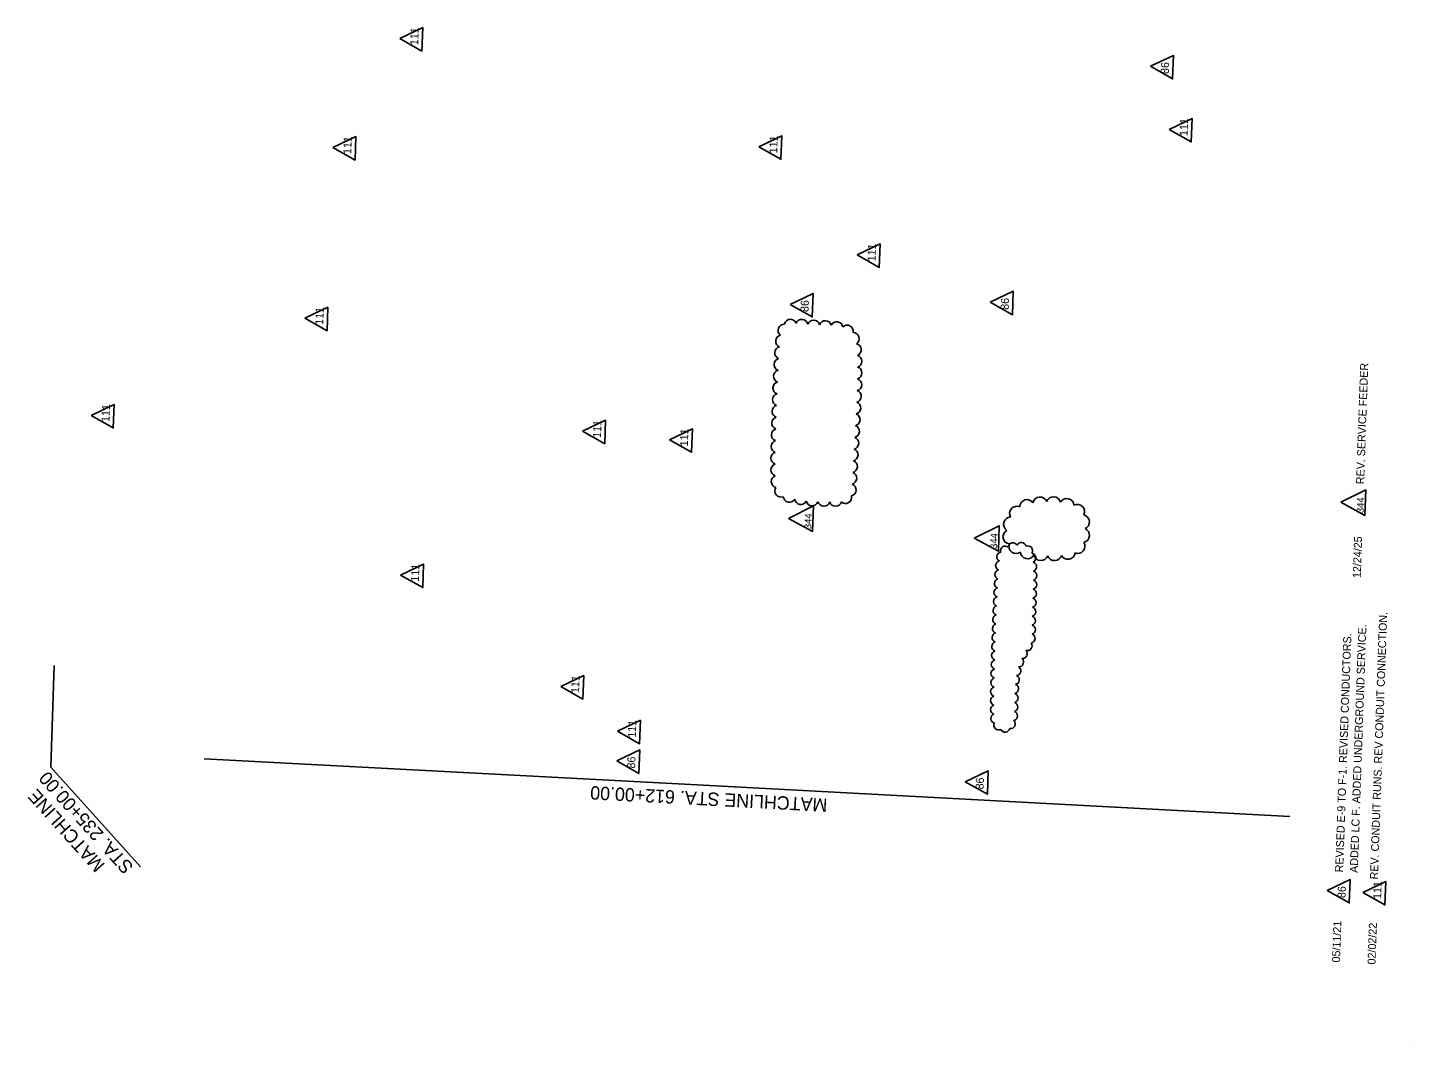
# Model space of a CAD drawing. Extents: x 928669 to 929521, y 636891 to 638153.
# Drawn here: x 928669 to 929497, y 636891 to 637500 of the extents above; entities that cross this region are included whole.
import ezdxf

# ---------------------------------------------------------------- set-up
doc = ezdxf.new("R2010")
doc.units = 0
for name, color, linetype in [('AdhocPoint_dp', 7, 'Continuous'), ('Cloud_dp', 7, 'Continuous'), ('PlotBorder_dp', 7, 'Continuous')]:
    doc.layers.add(name, color=color, linetype=linetype)

msp = doc.modelspace()

# ---------------------------------------------------------------- linework, layer by layer
at = {"layer": 'AdhocPoint_dp'}
msp.add_line((929497.23, 636890.88), (929497.23, 636890.88), dxfattribs=at)
at = {"layer": 'Cloud_dp'}
for points in [[(928892.18, 637493.38), (928905.49, 637485.87), (928905.98, 637499.95)], [(929342.46, 637476.74), (929355.77, 637469.23), (929356.26, 637483.31)], [(929353.7, 637438.9), (929367.01, 637431.39), (929367.5, 637445.47)], [(928852.01, 637428.07), (928865.32, 637420.55), (928865.81, 637434.63)], [(929107.53, 637428.51), (929120.84, 637421), (929121.33, 637435.07)], [(929166.5, 637363.72), (929179.81, 637356.21), (929180.3, 637370.28)], [(929126.34, 637333.99), (929139.65, 637326.48), (929140.14, 637340.55)], [(929246.44, 637335.3), (929259.74, 637327.79), (929260.24, 637341.87)], [(928835.21, 637325.69), (928848.52, 637318.18), (928849.01, 637332.25)], [(928706.97, 637267.46), (928720.28, 637259.95), (928720.77, 637274.02)], [(929001.81, 637257.92), (929015.12, 637250.41), (929015.62, 637264.49)], [(929053.95, 637252.83), (929067.26, 637245.32), (929067.75, 637259.4)], [(929456.7, 637215.31), (929471.17, 637207.46), (929471.71, 637222.78)], [(929125.38, 637205.69), (929139.85, 637197.84), (929140.4, 637213.16)], [(929236.82, 637193.83), (929251.29, 637185.99), (929251.84, 637201.3)], [(928892.62, 637171.72), (928905.92, 637164.21), (928906.42, 637178.28)], [(928988.69, 637104.86), (929001.99, 637097.34), (929002.49, 637111.42)], [(929022.71, 637078.07), (929036.02, 637070.56), (929036.51, 637084.63)], [(929022.35, 637060.26), (929035.66, 637052.75), (929036.15, 637066.82)], [(929231.39, 637047.73), (929244.7, 637040.22), (929245.19, 637054.29)], [(929448.5, 636982.61), (929461.8, 636975.1), (929462.3, 636989.17)], [(929469.81, 636981.4), (929483.12, 636973.89), (929483.61, 636987.96)]]:
    msp.add_lwpolyline(points, close=True, dxfattribs=at)
for centre, radius, start, end in [((929122.8, 637318.45), 3.69, 87.80017, 232.80017), ((929126.55, 637321.38), 3.69, 23.15755, 168.15755), ((929133.32, 637321.36), 3.69, 11.51014, 156.51014), ((929140.39, 637320.83), 3.69, 14.85135, 159.85135), ((929147.43, 637320.54), 3.69, 15.49782, 160.49782), ((929154.29, 637319.89), 3.69, 8.73713, 153.73713), ((929121.35, 637311.91), 3.69, 102.26773, 247.26773), ((929160.55, 637317.85), 3.69, 350.07913, 135.07913), ((929164.06, 637313.53), 3.69, 303.10209, 88.10209), ((929120.8, 637304.93), 3.69, 103.71595, 248.71595), ((929165.27, 637306.84), 3.69, 292.40552, 77.40552), ((929120.38, 637297.92), 3.69, 104.41777, 249.41777), ((929165.66, 637299.89), 3.69, 288.97914, 73.97914), ((929120.03, 637290.91), 3.69, 104.85392, 249.85392), ((929165.6, 637285.88), 3.69, 285.91131, 70.91131), ((929165.72, 637292.89), 3.69, 287.12059, 72.12059), ((929119.72, 637283.88), 3.69, 105.15885, 250.15885), ((929165.36, 637278.87), 3.69, 285.04439, 70.04439), ((929119.2, 637269.83), 3.69, 105.57058, 250.57058), ((929119.45, 637276.86), 3.69, 105.38753, 250.38753), ((929165.02, 637271.86), 3.69, 284.38636, 69.38636), ((929118.98, 637262.81), 3.69, 105.77043, 250.77043), ((929164.62, 637264.84), 3.69, 284.15826, 69.15826), ((929118.78, 637255.78), 3.69, 106.03107, 251.03107), ((929164.21, 637257.82), 3.69, 284.16856, 69.16856), ((929118.62, 637248.76), 3.69, 106.39157, 251.39157), ((929163.8, 637250.79), 3.69, 284.18212, 69.18212), ((929118.52, 637241.73), 3.69, 106.93873, 251.93873), ((929162.99, 637236.75), 3.69, 284.23075, 69.23075), ((929163.4, 637243.77), 3.69, 284.20115, 69.20115), ((929118.51, 637234.72), 3.69, 107.92679, 252.92679), ((929118.74, 637227.75), 3.69, 110.9032, 255.9032), ((929162.6, 637229.73), 3.69, 284.28717, 69.28717), ((929120.89, 637222.09), 3.69, 145.68846, 290.68846), ((929162.22, 637222.7), 3.69, 284.53316, 69.53316), ((929125.86, 637219.04), 3.69, 186.14464, 331.14464), ((929132.75, 637217.72), 3.69, 187.22191, 332.22191), ((929139.58, 637216.91), 3.69, 194.26719, 339.26719), ((929146.56, 637216.68), 3.69, 196.86603, 341.86603), ((929153.58, 637216.64), 3.69, 197.46796, 342.46796), ((929159.55, 637218.28), 3.69, 228.29205, 13.29205), ((929268.49, 637212.58), 4.34, 35.308, 180.308), ((929276.26, 637214.15), 4.34, 22.48218, 167.48218), ((929284.33, 637214.27), 4.34, 14.21001, 159.21001), ((929292.31, 637213.21), 4.34, 5.59978, 150.59978), ((929258.73, 637202.11), 4.34, 91.83987, 236.83987), ((929262.34, 637208.62), 4.34, 65.21552, 210.21552), ((929298.62, 637209.78), 4.34, 332.37306, 117.37306), ((929301.55, 637203.53), 4.34, 292.94928, 77.94928), ((929258.39, 637194.65), 4.34, 117.96985, 262.96985), ((929301.59, 637195.53), 4.34, 282.583, 67.583), ((929259.97, 637188.16), 2.83, 28.78334, 173.78334), ((929261.96, 637188.92), 4.34, 160.87737, 305.87737), ((929265.04, 637188.38), 2.83, 11.26339, 156.26339), ((929298.89, 637188.94), 4.33, 247.85066, 32.85066), ((929253.12, 637182.6), 2.83, 98.21199, 243.21199), ((929255.42, 637186.23), 2.83, 52.10778, 197.10778), ((929268.82, 637185.8), 4.34, 185.10829, 330.10829), ((929268.9, 637186.32), 2.83, 327.34776, 112.34776), ((929270.86, 637181.99), 2.83, 296.42176, 81.42176), ((929276.77, 637184.74), 4.34, 194.71107, 339.71107), ((929284.93, 637184.68), 4.34, 199.49595, 344.49595), ((929292.96, 637185.51), 4.34, 207.29676, 352.29676), ((929252.06, 637171.94), 2.83, 103.74095, 248.74095), ((929252.46, 637177.31), 2.83, 102.68653, 247.68653), ((929271.4, 637176.72), 2.83, 290.28256, 75.28256), ((929271.52, 637171.36), 2.83, 287.39433, 72.39433), ((929251.73, 637166.56), 2.83, 104.29457, 249.29457), ((929271.44, 637165.99), 2.83, 285.74847, 70.74847), ((929251.19, 637155.78), 2.83, 104.90417, 249.90417), ((929251.45, 637161.17), 2.83, 104.6505, 249.6505), ((929271.07, 637155.2), 2.83, 285.49782, 70.49782), ((929271.26, 637160.59), 2.83, 285.49782, 70.49782), ((929250.96, 637150.39), 2.83, 105.0968, 250.0968), ((929270.88, 637149.8), 2.83, 285.49782, 70.49782), ((929250.53, 637139.6), 2.83, 105.37448, 250.37448), ((929250.74, 637144.99), 2.83, 105.24953, 250.24953), ((929270.69, 637144.4), 2.83, 285.49782, 70.49782), ((929270.68, 637138.95), 2.83, 289.2147, 74.2147), ((929250.33, 637134.2), 2.83, 105.47977, 250.47977), ((929270.46, 637133.69), 2.83, 280.90735, 65.90735), ((929249.98, 637123.41), 2.83, 105.71597, 250.71597), ((929250.15, 637128.81), 2.83, 105.58748, 250.58748), ((929265.83, 637124.53), 2.83, 260.43465, 45.43465), ((929268.72, 637129.23), 2.83, 251.48331, 36.48331), ((929249.67, 637112.62), 2.83, 106.0666, 251.0666), ((929249.81, 637118.02), 2.83, 105.87187, 250.87187), ((929261.97, 637114.26), 2.83, 274.53949, 59.53949), ((929263.59, 637119.53), 2.83, 266.29935, 51.29935), ((929249.55, 637107.23), 2.83, 106.31958, 251.31958), ((929261.01, 637108.87), 2.83, 280.32638, 65.32638), ((929249.4, 637096.44), 2.83, 107.18967, 252.18967), ((929249.45, 637101.83), 2.83, 106.66732, 251.66732), ((929260.29, 637098.02), 2.83, 285.49782, 70.49782), ((929260.53, 637103.43), 2.83, 284.42974, 69.42974), ((929249.41, 637091.05), 2.83, 108.11302, 253.11302), ((929260.1, 637092.62), 2.83, 285.49782, 70.49782), ((929249.59, 637085.69), 2.83, 110.65574, 255.65574), ((929251.41, 637081.66), 2.83, 152.9623, 297.9623), ((929258.61, 637082.5), 2.83, 259.7863, 44.7863), ((929259.89, 637087.23), 2.83, 284.99439, 69.99439), ((929255.33, 637080.29), 2.83, 203.38501, 348.38501)]:
    msp.add_arc(centre, radius, start, end, dxfattribs=at)
at = {"layer": 'PlotBorder_dp'}
for p, q in [((928682.87, 637056.6), (928684.89, 637117.41)), ((928736.73, 636996.72), (928682.87, 637056.6))]:
    msp.add_line(p, q, dxfattribs=at)
msp.add_lwpolyline([(929426.17, 637026.85), (929066.68, 637046.02), (928774.81, 637061.58)], dxfattribs=at)

# ---------------------------------------------------------------- texts
at = {"layer": 'Cloud_dp'}
for s, height, p in [('111', 4.8, (928903.2, 637489.36)), ('86', 4.8, (929353.45, 637472.09)), ('111', 4.8, (929364.72, 637434.88)), ('111', 4.8, (928863.03, 637424.05)), ('111', 4.8, (929118.55, 637424.49)), ('111', 4.8, (929177.52, 637359.7)), ('111', 4.8, (928846.23, 637321.67)), ('86', 4.8, (929137.33, 637329.34)), ('86', 4.8, (929257.43, 637330.65)), ('REV. SERVICE FEEDER', 4.8, (929470.64, 637226.11)), ('111', 4.8, (928717.99, 637263.44)), ('111', 4.8, (929012.83, 637253.9)), ('111', 4.8, (929064.97, 637248.82)), ('344', 4.2, (929470.38, 637208.82)), ('344', 4.2, (929139.06, 637199.2)), ('344', 4.2, (929250.5, 637187.35)), ('12/24/25', 4.8, (929468.62, 637169.82)), ('111', 4.8, (928903.63, 637167.7)), ('REV. CONDUIT RUNS. REV CONDUIT CONNECTION.', 4.8, (929478.96, 636989.12)), ('ADDED LC F. ADDED UNDERGROUND SERVICE.', 4.8, (929466.85, 636993.06)), ('REVISED E-9 TO F-1. REVISED CONDUCTORS. ', 4.8, (929458.06, 636993.37)), ('111', 4.8, (928999.7, 637100.84)), ('111', 4.8, (929033.73, 637074.05)), ('86', 4.8, (929033.34, 637055.61)), ('86', 4.8, (929242.38, 637043.08)), ('86', 4.8, (929459.49, 636977.96)), ('111', 4.8, (929480.83, 636977.38)), ('05/11/21', 4.8, (929456.17, 636939.33)), ('02/02/22', 4.8, (929477.49, 636938.12))]:
    msp.add_text(s, height=height, rotation=87.99782, dxfattribs=at).set_placement(p)
at = {"layer": 'PlotBorder_dp'}
for s, rotation, p in [('STA. 235+00.00', 131.9666, (928732.88, 636996.98)), ('MATCHLINE', 131.9666, (928715.75, 636998.08)), ('MATCHLINE STA. 612+00.00', 176.94782, (929148.86, 637037.63))]:
    msp.add_text(s, height=8, rotation=rotation, dxfattribs=at).set_placement(p)

doc.saveas('drawing.dxf')
